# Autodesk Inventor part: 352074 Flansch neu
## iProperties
Created: 2006-10
Part Number: 352074 Flansch neu
Material: 2.0402.26
Description: Lagerbuchse ( geteilt)
Document SubType Name: Modeling
Designer: OSchmidt
Cost Center: 0,135 kg
Authority: 17197 mm^3
Density: 7.84 g/cm^3
HalbzeugNorm: DIN 1756
Abmessung: Rd. 50
Zweck: 267045
SaveDate: 2006-11-05
SaveTime: 21:14
TotalMass: 0,135 kg
TotalVolume: 17197 mm^3
Author: OSchmidt
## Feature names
1. Drehung1 [Revolution]
2. Bohrung2 [Hole]
3. Bohrung3 [Hole]
4. Runde Anordnung1 [Circular Pattern]
5. Spiegeln1 [Mirror]
